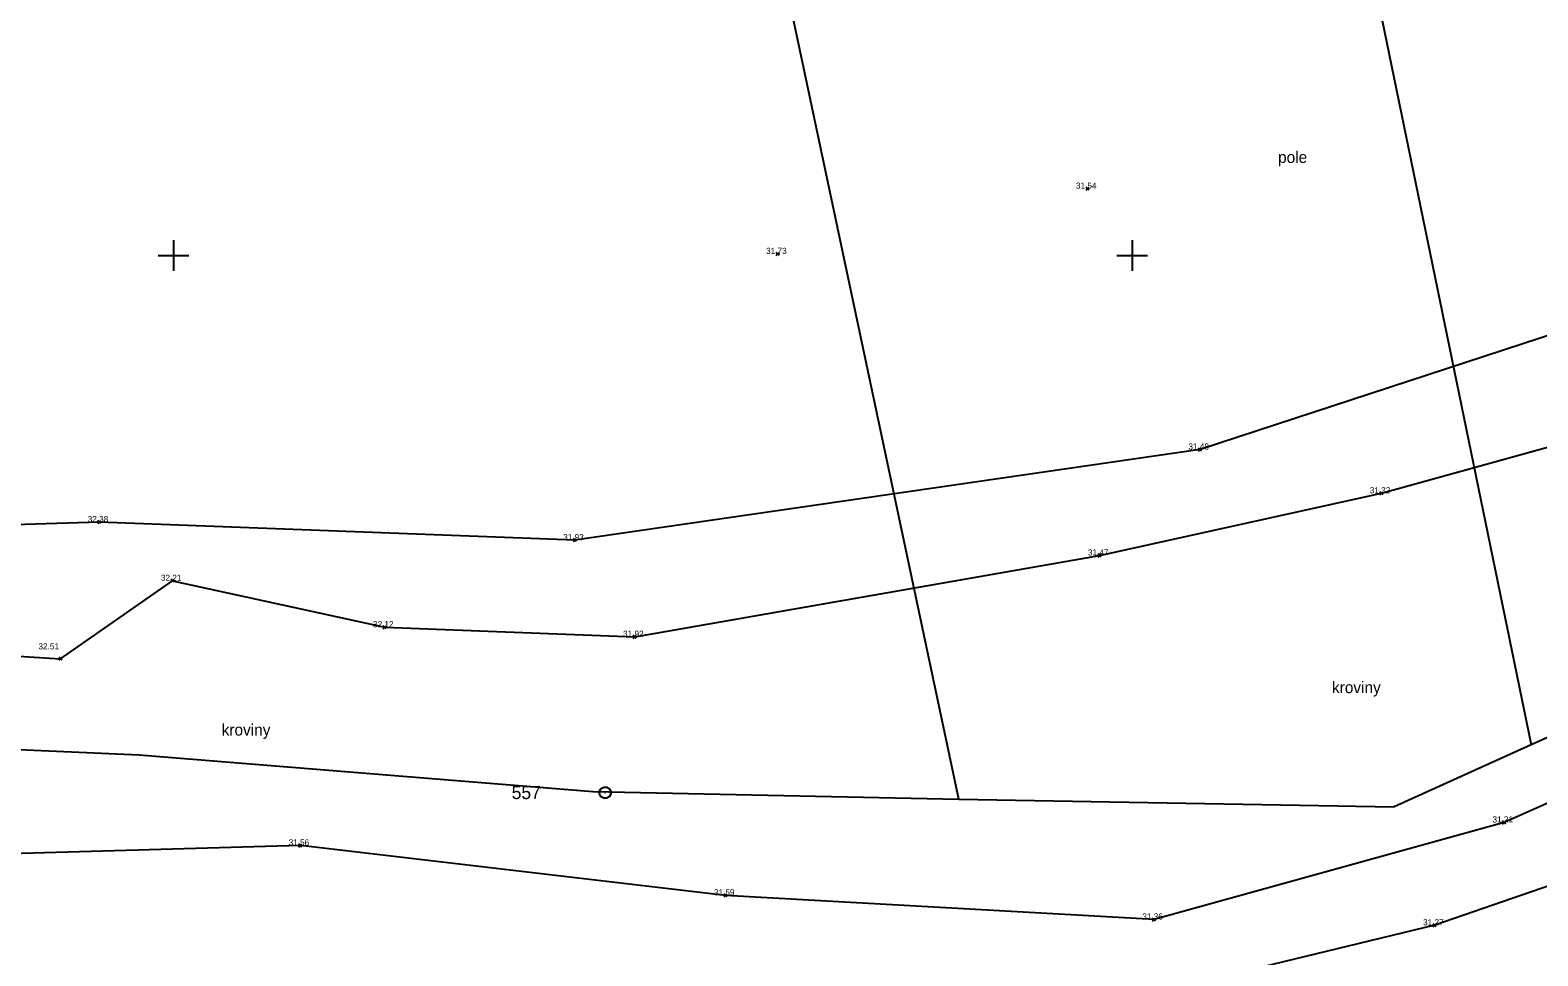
# Model space of a CAD drawing. Extents: x -772865 to -772533, y -1034366 to -1034132.
# Drawn here: x -772628.73 to -772589.42, y -1034218.26 to -1034194.13 of the extents above; entities that cross this region are included whole.
import ezdxf

# ---------------------------------------------------------------- set-up
doc = ezdxf.new("R2010")
doc.units = 0
for name, color, linetype in [('body', 7, 'Continuous'), ('KM_hranice', 7, 'Continuous'), ('KM_mezni_znaky', 7, 'Continuous'), ('mistni_popis', 7, 'Continuous'), ('oddeleni_ploch', 7, 'Continuous'), ('souradnicova_sit', 7, 'Continuous'), ('stromy_kere', 7, 'Continuous'), ('vyskove_koty', 7, 'Continuous')]:
    doc.layers.add(name, color=color, linetype=linetype)

msp = doc.modelspace()

# ---------------------------------------------------------------- linework, layer by layer
at = {"layer": 'body'}
for p, q in [((-772601.12, -1034198.3), (-772601.2, -1034198.22)), ((-772601.2, -1034198.3), (-772601.12, -1034198.22)), ((-772609.2, -1034200), (-772609.28, -1034199.92)), ((-772609.28, -1034200), (-772609.2, -1034199.92)), ((-772598.19, -1034205.1), (-772598.27, -1034205.02)), ((-772598.27, -1034205.1), (-772598.19, -1034205.02)), ((-772593.46, -1034206.24), (-772593.54, -1034206.16)), ((-772593.54, -1034206.24), (-772593.46, -1034206.16)), ((-772626.89, -1034206.99), (-772626.97, -1034206.91)), ((-772626.97, -1034206.99), (-772626.89, -1034206.91)), ((-772614.49, -1034207.46), (-772614.57, -1034207.38)), ((-772614.57, -1034207.46), (-772614.49, -1034207.38)), ((-772600.81, -1034207.86), (-772600.89, -1034207.78)), ((-772600.89, -1034207.86), (-772600.81, -1034207.78)), ((-772624.98, -1034208.52), (-772625.06, -1034208.44)), ((-772625.06, -1034208.52), (-772624.98, -1034208.44)), ((-772619.45, -1034209.73), (-772619.53, -1034209.65)), ((-772619.53, -1034209.73), (-772619.45, -1034209.65)), ((-772612.93, -1034209.98), (-772613.01, -1034209.9)), ((-772613.01, -1034209.98), (-772612.93, -1034209.9)), ((-772627.9, -1034210.55), (-772627.98, -1034210.47)), ((-772627.98, -1034210.55), (-772627.9, -1034210.47)), ((-772590.26, -1034214.82), (-772590.34, -1034214.74)), ((-772590.34, -1034214.82), (-772590.26, -1034214.74)), ((-772621.65, -1034215.42), (-772621.73, -1034215.34)), ((-772621.73, -1034215.42), (-772621.65, -1034215.34)), ((-772610.56, -1034216.72), (-772610.64, -1034216.64)), ((-772610.64, -1034216.72), (-772610.56, -1034216.64)), ((-772599.39, -1034217.35), (-772599.47, -1034217.27)), ((-772599.47, -1034217.35), (-772599.39, -1034217.27)), ((-772592.07, -1034217.5), (-772592.15, -1034217.42)), ((-772592.15, -1034217.5), (-772592.07, -1034217.42))]:
    msp.add_line(p, q, dxfattribs=at)
at = {"layer": 'KM_hranice'}
for p, q in [((-772604.52, -1034214.17), (-772617.5, -1034152.98)), ((-772594.95, -1034186.74), (-772589.6, -1034212.76)), ((-772549.99, -1034194.93), (-772589.6, -1034212.76)), ((-772642.11, -1034212.29), (-772625.89, -1034213.02)), ((-772625.89, -1034213.02), (-772614.06, -1034213.97)), ((-772589.6, -1034212.76), (-772593.17, -1034214.37)), ((-772614.06, -1034213.97), (-772604.52, -1034214.17)), ((-772604.52, -1034214.17), (-772593.17, -1034214.37))]:
    msp.add_line(p, q, dxfattribs=at)
at = {"layer": 'KM_mezni_znaky'}
msp.add_line((-772613.75, -1034214), (-772613.73, -1034214), dxfattribs=at)
msp.add_lwpolyline([(-772613.702, -1034213.856), (-772613.634, -1034213.894), (-772613.596, -1034213.962), (-772613.596, -1034214.04), (-772613.634, -1034214.108), (-772613.702, -1034214.146), (-772613.78, -1034214.146), (-772613.848, -1034214.108), (-772613.886, -1034214.04), (-772613.886, -1034213.962), (-772613.848, -1034213.894), (-772613.78, -1034213.856)], close=True, dxfattribs=at)
at = {"layer": 'oddeleni_ploch'}
for points in [[(-772574.1, -1034196.14), (-772586.87, -1034201.34), (-772598.23, -1034205.06), (-772614.53, -1034207.42), (-772626.93, -1034206.95), (-772636.66, -1034207.26), (-772647.96, -1034208.36), (-772659.39, -1034213.08), (-772672.58, -1034218.62), (-772687.49, -1034225.14), (-772703.01, -1034232.02), (-772714.35, -1034236.9), (-772728.88, -1034243.07), (-772737.97, -1034245.74), (-772746.8, -1034246.99), (-772753.85, -1034250.11), (-772762.71, -1034257.3), (-772782.05, -1034269.18), (-772797.09, -1034276.39), (-772810.61, -1034282.39), (-772816.13, -1034284.08), (-772822.76, -1034283.4), (-772826.73, -1034280.27)], [(-772569.67, -1034207.72), (-772578.35, -1034211.18), (-772588.33, -1034216.15), (-772592.11, -1034217.46), (-772598.89, -1034219.1), (-772610.21, -1034219.57), (-772621.14, -1034219.48), (-772637.34, -1034221.06), (-772647.54, -1034222.08), (-772674.34, -1034233.24), (-772685.01, -1034239.21), (-772697.33, -1034242.95), (-772712.12, -1034249.56), (-772725.85, -1034254.8), (-772738.85, -1034261.98), (-772750.37, -1034267.76), (-772764, -1034272.65), (-772783.9, -1034280.59), (-772796.38, -1034286.28), (-772810.31, -1034291.67), (-772823.61, -1034294.35), (-772828.52, -1034296.12), (-772827.01, -1034302.81), (-772823.23, -1034300.75)]]:
    msp.add_lwpolyline(points, dxfattribs=at)
at = {"layer": 'souradnicova_sit'}
for p, q in [((-772625, -1034199.6), (-772625, -1034200.4)), ((-772600, -1034199.6), (-772600, -1034200.4)), ((-772625.4, -1034200), (-772624.6, -1034200)), ((-772600.4, -1034200), (-772599.6, -1034200))]:
    msp.add_line(p, q, dxfattribs=at)
at = {"layer": 'stromy_kere'}
for points in [[(-772703.51, -1034234.42), (-772694.98, -1034230.19), (-772692.57, -1034230.49), (-772690.11, -1034226.84), (-772682.67, -1034224.98), (-772675.51, -1034221.67), (-772672.25, -1034219.76), (-772669.56, -1034219.99), (-772667.68, -1034217.27), (-772659.65, -1034214.88), (-772652.01, -1034211.79), (-772645.15, -1034209.57), (-772641.61, -1034208.89), (-772633.71, -1034210.15), (-772627.94, -1034210.51), (-772625.02, -1034208.48), (-772619.49, -1034209.69), (-772612.97, -1034209.94), (-772600.85, -1034207.82), (-772593.5, -1034206.2), (-772588.67, -1034204.86)], [(-772583.42, -1034211.72), (-772590.3, -1034214.78), (-772599.43, -1034217.31), (-772610.6, -1034216.68), (-772621.69, -1034215.38), (-772638.07, -1034215.85), (-772648.66, -1034218.46), (-772661.39, -1034222.42), (-772671.31, -1034228.13), (-772675.64, -1034228.98), (-772682.86, -1034232.81), (-772685.07, -1034236.11), (-772686.87, -1034236.8), (-772697.8, -1034241.28), (-772703.73, -1034242.07)]]:
    msp.add_lwpolyline(points, dxfattribs=at)

# ---------------------------------------------------------------- texts
at = {"layer": 'KM_mezni_znaky'}
msp.add_text('557', height=0.34, dxfattribs=at).set_placement((-772616.179, -1034214.17))
at = {"layer": 'mistni_popis'}
for s, p in [('pole', (-772596.196, -1034197.588)), ('kroviny', (-772594.79, -1034211.408)), ('kroviny', (-772623.741, -1034212.514))]:
    msp.add_text(s, height=0.3, dxfattribs=at).set_placement(p)
at = {"layer": 'vyskove_koty'}
for s, p in [('31.54', (-772601.465, -1034198.26)), ('31.73', (-772609.545, -1034199.96)), ('31.48', (-772598.535, -1034205.06)), ('31.32', (-772593.805, -1034206.2)), ('32.38', (-772627.235, -1034206.95)), ('31.93', (-772614.835, -1034207.42)), ('31.47', (-772601.155, -1034207.82)), ('32.21', (-772625.325, -1034208.48)), ('32.12', (-772619.795, -1034209.69)), ('31.92', (-772613.275, -1034209.94)), ('32.51', (-772628.518, -1034210.268)), ('31.21', (-772590.605, -1034214.78)), ('31.56', (-772621.995, -1034215.38)), ('31.59', (-772610.905, -1034216.68)), ('31.36', (-772599.735, -1034217.31)), ('31.27', (-772592.415, -1034217.46))]:
    msp.add_text(s, height=0.16, dxfattribs=at).set_placement(p)

doc.saveas('drawing.dxf')
